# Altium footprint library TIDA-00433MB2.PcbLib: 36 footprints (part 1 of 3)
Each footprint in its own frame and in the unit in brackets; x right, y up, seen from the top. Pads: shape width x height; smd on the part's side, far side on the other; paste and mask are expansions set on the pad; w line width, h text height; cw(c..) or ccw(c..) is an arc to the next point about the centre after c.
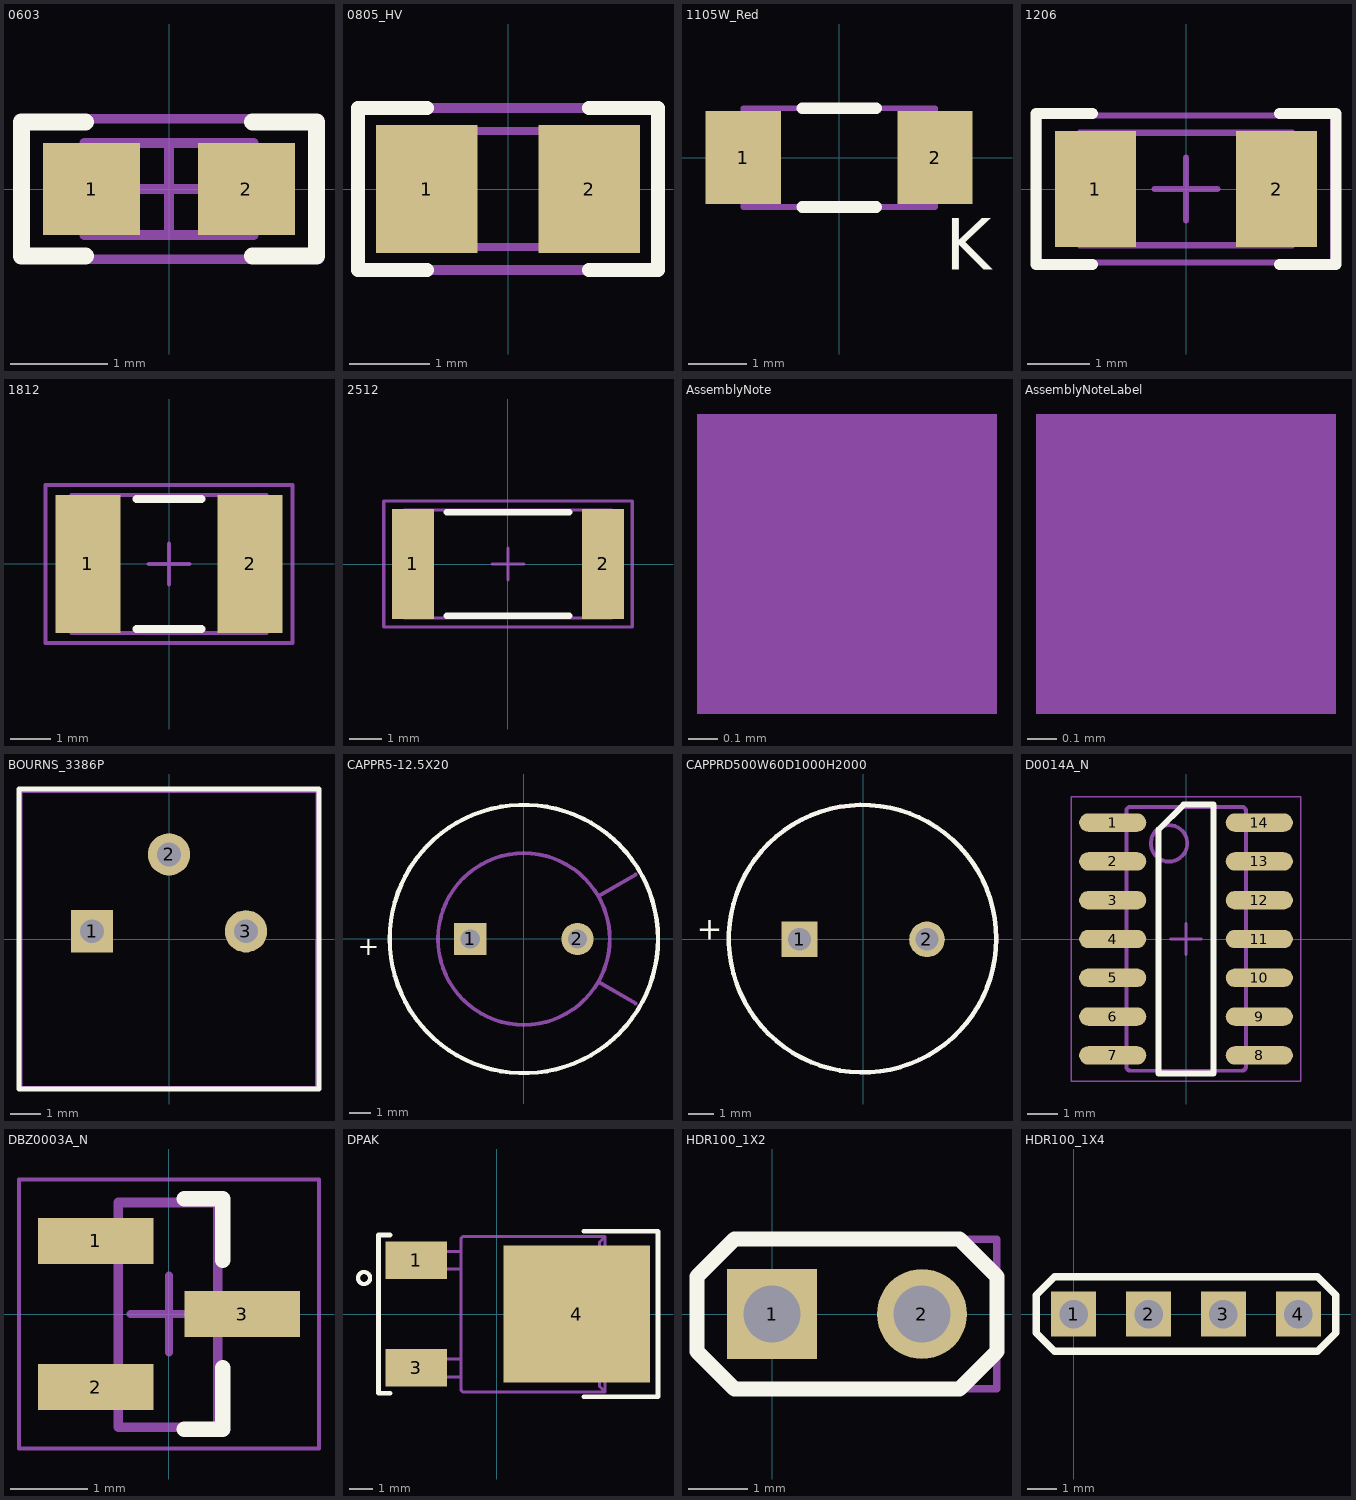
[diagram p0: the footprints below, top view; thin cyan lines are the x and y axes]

## 0603 [mm] "0603 from SM-752 data"
height 0.85
pads (2):
  rect 1x0.95 smd: 1(-0.8,0) 2(0.8,0)
Top Overlay:
  lines w0.178: -0.864,-0.691 -1.524,-0.691 -1.524,0.693 -0.864,0.693 ; 0.864,-0.691 1.524,-0.691 1.524,0.693 0.864,0.693
Mechanical 5:
  lines w0.1: -1.55,-0.725 1.55,-0.725 1.55,0.725 -1.55,0.725 -1.55,-0.725
  text ".Designator" at 0.94,0.381 h0.89
Mechanical 13:
  lines w0.1: -0.55,-0.475 -0.55,0.475 ; 0.55,-0.475 0.55,0.475 ; -0.875,-0.475 -0.875,0.475 0.875,0.475 0.875,-0.475 -0.875,-0.475
Mechanical 15:
  lines w0.1: -0.475,0 0.475,0 ; 0,-0.475 0,0.475 ; -1.55,-0.725 -1.55,0.725 1.55,0.725 1.55,-0.725 -1.55,-0.725
3D body: height 0.85, standoff 0, extent 0.551,-0.474 0.874,0.474
3D body: height 0.85, standoff 0, extent -0.549,-0.474 0.549,0.474
3D body: height 0.85, standoff 0, extent -0.874,-0.474 -0.551,0.474

## 0805_HV [mil] "0805 with 30mil clearance between pads"
height 43.31
pads (2):
  rect 50x63 smd: 1(-40,0) 2(40,0)
Top Overlay:
  lines w7: -40,-40 -74,-40 -74,0 -74,40 -40,40 ; 40,-40 74,-40 74,0 74,40 40,40
Mechanical 5:
  lines w5: -74,-40 74,-40 74,40 -74,40 -74,-40
  text ".Designator" at -64,-17 h35
Mechanical 13:
  lines w3.94: -25.59,-28.54 -25.59,28.54 ; 25.59,-28.54 25.59,28.54 ; -43.31,-28.54 -43.31,28.54 43.31,28.54 43.31,-28.54 -43.31,-28.54
3D body: height 43.31, standoff 0, extent 25.61,-28.52 43.29,28.52
3D body: height 43.31, standoff 0, extent -25.57,-28.52 25.57,28.52
3D body: height 43.31, standoff 0, extent -43.29,-28.52 -25.61,28.52

## 1105W_Red [mm] "Stanley Electric Co"
height 2.05
pads (2):
  rect 1.3x1.6 smd: 1(-1.65,0) 2(1.65,0)
Top Overlay:
  lines w0.2: -0.635,-0.85 0.635,-0.85 ; -0.635,0.85 0.635,0.85
  text "K" at 1.829,-1.93 h0.89
Mechanical 5:
  lines w0.1: -1.65,-0.85 -1.65,0.85 1.65,0.85 1.65,-0.85 -1.65,-0.85
  text ".Designator" at -1.2,-0.3 h0.89
  text "K" at 1,-2 h0.89
3D body: height 0.4, standoff 0, extent -1.65,-0.85 1.65,0.85
3D body: height 2.05, standoff 0.45, extent -0.792,-0.797 0.8,0.797
3D body: height 1.25, standoff 0.4, extent -0.794,-0.798 0.8,0.799
3D body: height 0.41, standoff 0.4, extent 0.902,0.401 1.3,0.8

## 1206 [mm] "1206 from SM-752 data"
height 1.35
pads (2):
  rect 1.3x1.85 smd: 1(-1.45,0) 2(1.45,0)
Top Overlay:
  lines w0.178: -1.5,-1.21 -2.4,-1.21 -2.4,1.21 -1.5,1.21 ; 1.5,-1.21 2.4,-1.21 2.4,1.21 1.5,1.21
Mechanical 5:
  lines w0.1: -1.7,-0.9 -1.7,0.9 1.7,0.9 1.7,-0.9 -1.7,-0.9
  text ".Designator" at -0.787,-0.406 h0.89
Mechanical 13:
  lines w0.1: -1.2,-0.9 -1.2,0.9 ; 1.2,-0.9 1.2,0.9 ; -1.7,-0.9 -1.7,0.9 1.7,0.9 1.7,-0.9 -1.7,-0.9
Mechanical 15:
  lines w0.1: -0.5,0 0.5,0 ; 0,-0.5 0,0.5 ; -2.35,-1.175 -2.35,1.175 2.35,1.175 2.35,-1.175 -2.35,-1.175
3D body: height 1.35, standoff 0, extent 1.201,-0.899 1.699,0.899
3D body: height 1.35, standoff 0, extent -1.199,-0.899 1.199,0.899
3D body: height 1.35, standoff 0, extent -1.699,-0.899 -1.201,0.899

## 1812 [mm]
height 1.35
pads (2):
  rect 1.6x3.4 smd: 1(-2,0) 2(2,0)
Top Overlay:
  lines w0.2: -0.8,-1.6 0.8,-1.6 ; -0.8,1.6 0.8,1.6
Mechanical 5:
  lines w0.1: -2.4,-1.7 -2.4,1.7 2.4,1.7 2.4,-1.7 -2.4,-1.7
  text ".Designator" at -0.889,0.965 h0.89
Mechanical 13:
  lines w0.1: -1.9,-1.7 -1.9,1.7 ; 1.9,-1.7 1.9,1.7 ; -2.4,-1.7 2.4,-1.7 2.4,1.7 -2.4,1.7 -2.4,-1.7
Mechanical 15:
  lines w0.1: -0.5,0 0.5,0 ; 0,-0.5 0,0.5 ; -3.05,-1.95 3.05,-1.95 3.05,1.95 -3.05,1.95 -3.05,-1.95
3D body: height 1.35, standoff 0, extent 1.901,-1.699 2.399,1.699
3D body: height 1.35, standoff 0, extent -1.899,-1.699 1.899,1.699
3D body: height 1.35, standoff 0, extent -2.399,-1.699 -1.901,1.699

## 2512 [mm] "Chip Resistor, Body 6.3x3.2mm, IPC Medium Density"
height 0.71
pads (2):
  rect 1.3x3.4 smd: 1(-2.95,0) 2(2.95,0)
Top Overlay:
  lines w0.2: -1.9,-1.6 1.9,-1.6 ; -1.9,1.6 1.9,1.6
Mechanical 5:
  lines w0.1: -3.225,-1.675 3.225,-1.675 3.225,1.675 -3.225,1.675 -3.225,-1.675
  text ".Designator" at -1.295,-0.457 h0.89
Mechanical 13:
  lines w0.1: -2.463,-1.675 -2.463,1.675 ; 2.463,-1.675 2.463,1.675 ; -3.225,-1.675 3.225,-1.675 3.225,1.675 -3.225,1.675 -3.225,-1.675
Mechanical 15:
  lines w0.1: -0.5,0 0.5,0 ; 0,-0.5 0,0.5 ; -3.85,-1.95 3.85,-1.95 3.85,1.95 -3.85,1.95 -3.85,-1.95
3D body: height 0.71, standoff 0, extent -3.224,-1.674 -2.464,1.674
3D body: height 0.71, standoff 0, extent -2.462,-1.674 2.462,1.674
3D body: height 0.71, standoff 0, extent 2.464,-1.674 3.224,1.674

## AssemblyNote [mil] "Assembly Note"
Mechanical 5:
  rectangle: 614,3222 654,3262
  text ".Designator" at 469,3213 h35
  text ".Comment" at 684,3223 h35

## AssemblyNoteLabel [mil] "Assembly Note for PCB Labels"
Mechanical 5:
  rectangle: 622,3297 662,3337
  text "Install label in silkscreened box after final wash.  Text shall be 8 pt font.  Text shall be per the Label Table in the PDF schematic." at 699,3303 h35
  text ".Designator" at 469,3301 h35

## BOURNS_3386P [mil] "BOURND"
height 200
pads (3):
  rect 55x55 hole 31: 1(-100,10)
  round 55 hole 31: 2(0,110) 3(100,10)
Top Overlay:
  lines w6: -195,-195 195,-195 195,195 -195,195 -195,-195
Mechanical 5:
  lines w4: -192.5,-193 192,-193 192.5,192 -192.5,192 -192.5,-193
  text ".Designator" at -10,34 h35
3D body: height 201, standoff 0, extent -55.41,-50.41 45.41,50.41
3D body: height 200, standoff 0, extent -192.52,-193.02 192.52,192.02
3D body: height 50, standoff -200, extent -10.91,99.02 11,120.97
3D body: height 50, standoff -200, extent -110.91,-0.98 -89,20.98
3D body: height 50, standoff -200, extent 89.09,-0.98 111,20.98

## CAPPR5-12.5X20 [mm] "Capacitor, Electrolytic, Radial; Body 12.5 x 20 mm (Dia.xH typ); Pin Spacing 5 mm (typ)"
height 22
pads (2):
  rect 1.5x1.5 hole 0.9: 1(-2.5,0)
  round 1.5 hole 0.9: 2(2.5,0)
Top Overlay:
  circle w0.2: c0,0 r6.25
  text "+" at -7.725,-0.75 h0.89
Mechanical 5:
  circle w0.127: c0,0 r6.25
  text "+" at -7.725,-0.75 h0.89
  text ".Designator" at 0.279,-1.397 h0.89
Mechanical 13:
  circle w0.178: c0,0 r4
  circle w0.178: c-2.5,0 r0.3
  circle w0.178: c2.5,0 r0.3
  lines w0.178: 3.464,-2 5.196,-3 ; 3.464,2 5.196,3
3D body: height 22, standoff 0, extent -4.013,-4.013 5.197,4.013
3D body: height 22, standoff 0, extent -6.01,-6.01 5.197,6.01
3D body: height 22, standoff 0, extent 3.463,-3.001 6.01,3.001
3D body: height 1, standoff -2.54, extent -2.805,-0.305 -2.195,0.305
3D body: height 1, standoff -2.54, extent 2.195,-0.305 2.805,0.305

## CAPPRD500W60D1000H2000 [mm] "Capacitor, Electrolytic, Radial; Body 10 x 20 mm (Dia.xH typ); Pin Spacing 5 mm (typ)"
height 21.5
pads (2):
  rect 1.4x1.4 hole 0.889: 1(-2.5,0)
  round 1.4 hole 0.889: 2(2.5,0)
Top Overlay:
  circle w0.178: c-0.025,0.025 r5.25
  text "+" at -6.525,0.75 h0.89
Mechanical 5:
  circle w0.1: c0,0 r5.25
  text ".Designator" at -1.067,0.432 h0.89
  text "+" at -6.548,0.75 h0.89
3D body: height 22.01, standoff -4, extent -5.209,-5.241 5.24,5.242

## D0014A_N [mm] "SOIC, 14-Leads, Body 8.7x3.9mm, Pitch 1.27mm, IPC Medium Density"
height 1.75
pads (14):
  oval 2.2x0.6 smd: 1(-2.4,3.81) 2(-2.4,2.54) 3(-2.4,1.27) 4(-2.4,0) 5(-2.4,-1.27) 6(-2.4,-2.54) 7(-2.4,-3.81) 8(2.4,-3.81) 9(2.4,-2.54) 10(2.4,-1.27) 11(2.4,0) 12(2.4,1.27) 13(2.4,2.54) 14(2.4,3.81)
Top Overlay:
  lines w0.2: -0.9,-4.4 0.9,-4.4 0.9,4.4 -0.075,4.4 -0.9,3.575 -0.9,-4.4
Mechanical 5:
  drawing of 164 lines, arcs and shapes, not listed
  text ".Designator" at 0.496,0.271 h0.89
Mechanical 15:
  lines w0.05: -3.75,-4.65 3.75,-4.65 3.75,4.65 -3.75,4.65 -3.75,-4.65
  lines w0.1: -0.5,0 0.5,0 ; 0,-0.5 0,0.5
3D body: height 1.59, standoff -0.01, extent -3.023,-4.318 3.022,4.318

## DBZ0003A_N [mm] "SOT23, 3-Leads, Body 2.9x1.3mm, Pitch 0.95mm, Lead Span 2.4mm, IPC Medium Density"
height 1.12
pads (3):
  rect 1.5x0.6 smd: 1(-0.95,0.95) 2(-0.95,-0.95) 3(0.95,0)
Top Overlay:
  lines w0.2: 0.2,-1.5 0.7,-1.5 0.7,-0.7 ; 0.2,1.5 0.7,1.5 0.7,0.7
Mechanical 5:
  lines w0.127: -1.27,-1.187 -1.27,-0.743 -1.063,-0.743 -1.005,-0.743 -0.814,-0.743 -0.66,-0.743 -0.66,-1.187 -0.814,-1.187 -1.005,-1.187 -1.063,-1.187 -1.27,-1.187 ; -1.27,0.718 -1.27,1.162 -1.063,1.162 -1.005,1.162 -0.814,1.162 -0.66,1.162 -0.66,0.718 -0.814,0.718 -1.005,0.718 -1.063,0.718 -1.27,0.718 ; -0.66,-1.473 -0.66,1.448 0.635,1.448 0.635,-1.473 -0.66,-1.473 ; 0.635,-0.235 0.789,-0.235 0.98,-0.235 1.037,-0.235 1.245,-0.235 1.245,0.21 1.037,0.21 0.98,0.21 0.789,0.21 0.635,0.21 0.635,-0.235
  text ".Designator" at -0.432,0.711 h0.89
Mechanical 15:
  lines w0.05: -1.95,-1.75 -1.95,1.75 1.95,1.75 1.95,-1.75 -1.95,-1.75
  lines w0.1: -0.5,0 0.5,0 ; 0,-0.5 0,0.5
3D body: height 0.96, standoff -0.02, extent -1.257,-1.461 1.257,1.46

## DPAK [mm] "D-PAK, 3-Pads, Body 6.22x6.73mm (max), TO-252AA using nominal STEP model"
height 2.39
pads (3):
  rect 2.6x1.6 smd: 1(-3.4,2.28) 3(-3.4,-2.28)
  rect 6.2x5.8 smd paste-2.9: 4(3.4,0)
Top Overlay:
  circle w0.178: c-5.614,1.524 r0.254
  lines w0.2: -4.502,-3.354 -5,-3.354 -5,3.346 -4.502,3.346 ; 3.688,-3.5 6.834,-3.5 6.834,3.5 3.688,3.5
Top Paste:
  rectangle: 0.4,-2.8 1.675,-1.625
  rectangle: 1.975,-2.8 3.25,-1.625
  rectangle: 3.55,-2.8 4.825,-1.625
  rectangle: 5.125,-2.8 6.4,-1.625
  rectangle: 5.125,-1.325 6.4,-0.15
  rectangle: 3.55,-1.325 4.825,-0.15
  rectangle: 1.975,-1.325 3.25,-0.15
  rectangle: 0.4,-1.325 1.675,-0.15
  rectangle: 5.125,0.15 6.4,1.325
  rectangle: 3.55,0.15 4.825,1.325
  rectangle: 1.975,0.15 3.25,1.325
  rectangle: 0.4,0.15 1.675,1.325
  rectangle: 5.125,1.625 6.4,2.8
  rectangle: 3.55,1.625 4.825,2.8
  rectangle: 1.975,1.625 3.25,2.8
  rectangle: 0.4,1.625 1.675,2.8
Mechanical 5:
  lines w0.127: -1.5,1.9 -2.757,1.9 -3.157,1.9 ; -1.5,2.65 -2.757,2.65 -3.157,2.65 ; -3.899,-2.665 -3.899,-1.915 ; -3.899,-2.665 -3.357,-2.665 ; -3.899,-2.665 -3.899,-1.915 ; -3.899,-2.665 -3.357,-2.665 ; -3.899,-2.665 -3.899,-1.915 ; -3.899,-2.665 -3.357,-2.665 ; -3.899,-1.915 -3.357,-1.915 ; -3.899,-1.915 -3.357,-1.915 ; -3.899,-1.915 -3.357,-1.915 ; -3.357,-2.665 -3.157,-2.665 ; -3.357,-2.665 -3.157,-2.665 ; -3.357,-2.665 -3.157,-2.665 ; -3.357,-1.915 -3.157,-1.915 ; -3.357,-1.915 -3.157,-1.915 ; -3.357,-1.915 -3.157,-1.915 ; -3.157,-2.665 -2.757,-2.665 ; -3.157,-2.665 -3.157,-1.915 ; -3.157,-2.665 -2.757,-2.665 ; -3.157,-2.665 -3.157,-1.915 ; -3.157,-2.665 -2.757,-2.665 ; -3.157,-2.665 -3.157,-1.915 ; -3.157,-1.915 -2.757,-1.915 ; -3.157,-1.915 -2.757,-1.915 ; -3.157,-1.915 -2.757,-1.915 ; -3.157,1.9 -3.157,2.65 ; -3.157,1.9 -3.357,1.9 -3.899,1.9 -3.899,2.65 -3.357,2.65 -3.157,2.65 ; -2.757,-2.665 -1.5,-2.665 ; -2.757,-2.665 -1.5,-2.665 ; -2.757,-2.665 -1.5,-2.665 ; -2.757,-1.915 -1.5,-1.915 ; -2.757,-1.915 -1.5,-1.915 ; -2.757,-1.915 -1.5,-1.915 ; -1.5,-2.665 -1.5,-3.157 -1.5,-3.229 -1.429,-3.3 4.6,-3.3 ; -1.5,-2.665 -1.5,-1.915 ; -1.5,-2.665 -1.5,-1.915 ; -1.5,-2.665 -1.5,-1.915 ; -1.5,-1.915 -1.5,3.137 -1.5,3.209 -1.429,3.28 4.6,3.28 ; 4.6,-3.3 4.348,-3.048 4.348,3.028 4.6,3.28 ; 4.6,-3.3 4.6,-2.69 5.8,-2.69 5.8,-2.01 5.308,-2.01 5.308,1.99 5.8,1.99 5.8,2.67 4.6,2.67 4.6,3.28
  text ".Designator" at 2.388,0.406 h0.89
3D body: height 0.36, standoff -2.12, extent -3.856,-3.29 5.843,3.29

## HDR100_1X2 [mil]
pads (2):
  rect 60x60 hole 38: 1(0,0)
  round 60 hole 38: 2(100,0)
Top Overlay:
  lines w10: -50,-25 -25,-50 125,-50 150,-25 150,25 125,50 -25,50 -50,25 -50,-25
Mechanical 5:
  lines w5: -50,-25 -50,25 -25,50 150,50 150,-50 -25,-50 -50,-25
  text ".Designator" at 166,32 h35

## HDR100_1X4 [mil]
pads (4):
  rect 60x60 hole 38: 1(0,0) 2(100,0) 3(200,0) 4(300,0)
Top Overlay:
  lines w10: -50,-25 -25,-50 325,-50 350,-25 350,25 325,50 -25,50 -50,25 -50,-25
Mechanical 5:
  lines w5: -50,-25 -25,-50 325,-50 350,-25 350,25 325,50 -25,50 -50,25 -50,-25
  text ".Designator" at 60,63 h35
